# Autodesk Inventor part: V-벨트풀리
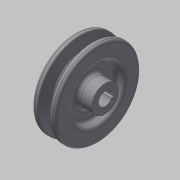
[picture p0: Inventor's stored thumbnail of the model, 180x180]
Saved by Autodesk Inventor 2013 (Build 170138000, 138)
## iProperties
Created: 2015-02
Part Number: V-벨트풀리
Material: 일반
Document SubType Name: Modeling
Designer: Administrator
Density: 1 g/cm^3
Author: Administrator
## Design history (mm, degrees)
sketch "스케치1"
  geometry: L1 (0, 0)-(25, 0); L2 (0, 5.5)-(0, 11); L3 (0, 11)-(6, 11); L4 (6, 11)-(6, 21.5); L5 (6, 21.5)-(0, 21.5); L6 (0, 21.5)-(0, 35.2); L7 (0, 35.2)-(4.675, 35.2); L8 (4.675, 35.2)-(7.426, 26.2); L9 (7.426, 26.2)-(11.574, 26.2); L10 (11.574, 26.2)-(14.325, 35.2); L11 (14.325, 35.2)-(19, 35.2); L12 (19, 35.2)-(19, 21.5); L13 (19, 21.5)-(13, 21.5); L14 (13, 21.5)-(13, 11); L15 (13, 11)-(25, 11); L16 (25, 7.894)-(25, 5.5); L17 (5.5, 32.5)-(13.5, 32.5); L18 (25, 11)-(25, 5.5); L19 (0, 5.5)-(25, 5.5); 2 further points
  constraints: 38 end point, 9 parallel, 5 collinear, 5 perpendicular, 4 vertical alignment, 2 midpoint, 2 point on line, 1 horizontal
  dimensions: "d0" = 25 distance of L1.start L1.end; "d5" = 43 diameter of L5 L1; "d6" = 65 diameter of L17 L1; "d7" = 2.7 distance between parallel lines of L7 L17; "d8" = 6.3 distance between parallel lines of L9 L17; "d9" = 34 deg angle of L10 L8; "d10" = 8 distance of L17.start L17.end; "d11" = 19 distance between parallel lines of L6 L12; "d12" = 22 diameter of L3 L1; "d13" = 6 distance between parallel lines of L14 L12; "d14" = 6 distance between parallel lines of L4 L6; "d16" = 11 diameter of L19 L1
revolve "회전1" sketch "스케치1" stored, may be unused: angle "d15" = 90 deg
sketch "스케치2"
  geometry: L1 (25, -5.5)-(0, -5.5) reference; L2 (0, 0)-(25, 0); L3 (25, 0)-(25, 7.3); L4 (25, 7.3)-(0, 7.3); L5 (0, 7.3)-(0, 0)
  constraints: 8 end point, 2 parallel, 1 horizontal, 1 perpendicular, 1 vertical alignment
  dimensions: "d17" = 12.8 distance between parallel lines of L1 L4
extrude "돌출1" cut sketch "스케치2" stored distance "d18" = 4; taper "d19" = 0 deg
fillet "모깎기1" dims "d20" = 1
fillet "모깎기2" dims "d21" = 0.5
fillet "모깎기3" dims "d22" = 2
fillet "모깎기4" dims "d23" = 3
node "솔리드1"
other parameters: "d2" = 2.7, "d3" = 6.3, "d4" = 65
